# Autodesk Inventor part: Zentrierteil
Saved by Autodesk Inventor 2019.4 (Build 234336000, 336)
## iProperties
Created: 2021-06
Part Number: Zentrierteil
Material: Generic
Document SubType Name: Modeling
Designer: Administrator
Density: 1 g/cm^3
Appearance: Default
Title: Zentrierteil v10
Author: Administrator
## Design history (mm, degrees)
feature "Body1"
body "Solid1"
